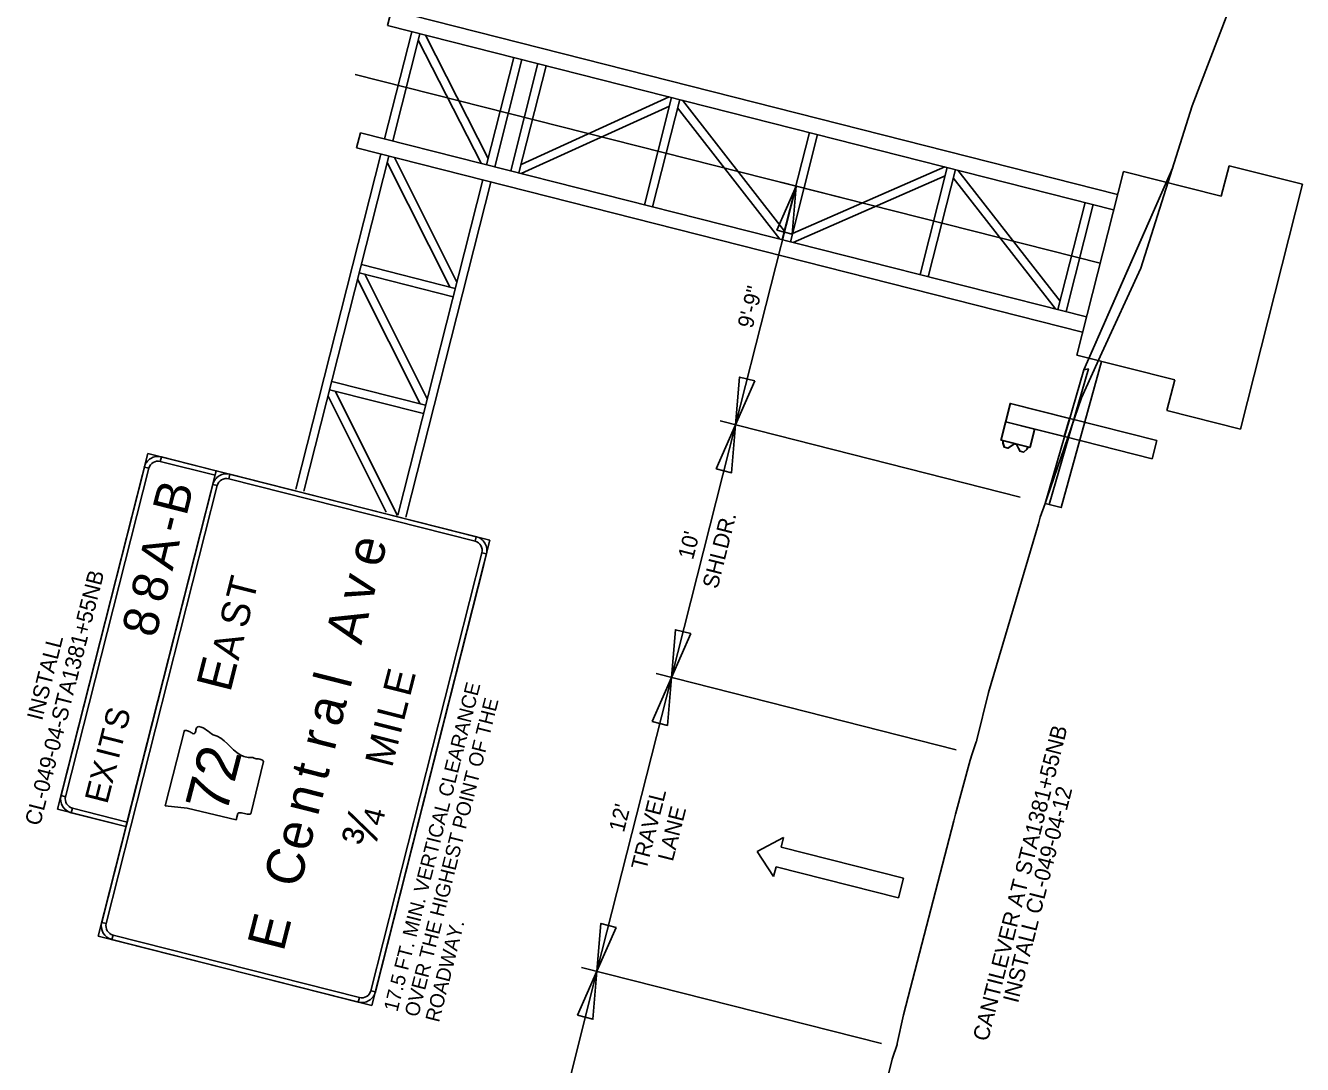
# Model space of a CAD drawing. Extents: x 670006 to 670131, y 737844 to 738002.
# Drawn here: x 670068.6 to 670119.1, y 737920.9 to 737962 of the extents above; entities that cross this region are included whole.
import ezdxf

# ---------------------------------------------------------------- set-up
doc = ezdxf.new("R2010")
doc.units = 0
for name, color, linetype in [('R_Alt Surface', 7, 'Continuous'), ('R_Exist Surface', 7, 'Continuous'), ('R_Fin Surface', 7, 'Continuous'), ('R_Guardrail', 7, 'Continuous'), ('R_MOT', 7, 'Continuous'), ('R_Proposed Const Limits', 7, 'Continuous'), ('R_SIGN', 7, 'Continuous'), ('R_SIGN_ANNOT', 7, 'Continuous')]:
    doc.layers.add(name, color=color, linetype=linetype)

msp = doc.modelspace()

# ---------------------------------------------------------------- linework, layer by layer
at = {"layer": 'R_Alt Surface'}
msp.add_lwpolyline([(670109.08, 737943.044), (670109.565, 737942.921), (670111.156, 737948.707)], dxfattribs=at)
at = {"layer": 'R_Exist Surface'}
msp.add_lwpolyline([(670101.41, 737915.266), (670102.87, 737921.083), (670102.88, 737921.115), (670103.063, 737921.667), (670103.071, 737921.706), (670103.315, 737922.841), (670105.306, 737930.515), (670105.374, 737930.778), (670105.958, 737932.918), (670105.978, 737932.992), (670105.979, 737932.995), (670106.006, 737933.094), (670106.197, 737933.644), (670106.205, 737933.663), (670106.219, 737933.721), (670106.688, 737935.597), (670108.659, 737942.277), (670108.734, 737942.533), (670108.919, 737943.085), (670109.001, 737943.32), (670110.364, 737947.269), (670111.175, 737949.039), (670112.711, 737952.403), (670113.874, 737956.065), (670114.748, 737958.822), (670116.463, 737963.305)], dxfattribs=at)
at = {"layer": 'R_Fin Surface'}
for points in [[(670108.919, 737943.085), (670110.458, 737948.368), (670112.079, 737952.061), (670113.975, 737956.382)], [(670108.919, 737943.085), (670110.458, 737948.368)]]:
    msp.add_lwpolyline(points, dxfattribs=at)
msp.add_lwpolyline([(670108.919, 737943.085), (670109.08, 737943.044), (670110.64, 737948.408), (670110.458, 737948.368)], close=True, dxfattribs=at)
at = {"layer": 'R_Guardrail'}
for points in [[(670107.355, 737946.318), (670107.539, 737947.045), (670109.885, 737946.45), (670109.672, 737945.731)], [(670107.355, 737946.318), (670107.539, 737947.045), (670109.885, 737946.45), (670109.672, 737945.731)], [(670107.368, 737946.315), (670107.552, 737947.042), (670109.898, 737946.447), (670109.688, 737945.727)], [(670107.171, 737945.591), (670107.355, 737946.318), (670108.5, 737946.028), (670108.315, 737945.301)], [(670107.171, 737945.591), (670107.355, 737946.318), (670108.5, 737946.028), (670108.315, 737945.301)], [(670107.184, 737945.588), (670107.368, 737946.315), (670108.513, 737946.025), (670108.329, 737945.298)], [(670107.247, 737945.572), (670107.244, 737945.471), (670107.306, 737945.308), (670107.445, 737945.273), (670107.696, 737945.445), (670107.784, 737945.422), (670107.923, 737945.151), (670108.062, 737945.116), (670108.194, 737945.23), (670108.239, 737945.32)], [(670107.247, 737945.572), (670107.244, 737945.471), (670107.306, 737945.308), (670107.445, 737945.273), (670107.696, 737945.445), (670107.784, 737945.422), (670107.923, 737945.151), (670108.062, 737945.116), (670108.194, 737945.23), (670108.239, 737945.32)], [(670107.26, 737945.569), (670107.257, 737945.468), (670107.319, 737945.305), (670107.458, 737945.269), (670107.709, 737945.441), (670107.797, 737945.419), (670107.936, 737945.148), (670108.075, 737945.113), (670108.207, 737945.227), (670108.252, 737945.317)]]:
    msp.add_lwpolyline(points, close=True, dxfattribs=at)
for points in [[(670113.158, 737944.846), (670109.688, 737945.727), (670109.898, 737946.447), (670113.343, 737945.573)], [(670113.158, 737944.846), (670113.343, 737945.573)]]:
    msp.add_lwpolyline(points, dxfattribs=at)
at = {"layer": 'R_MOT'}
for p, q in [((670098.568, 737929.861), (670097.521, 737929.302)), ((670098.469, 737929.474), (670098.568, 737929.861)), ((670097.521, 737929.302), (670098.174, 737928.31)), ((670103.312, 737928.245), (670098.469, 737929.474)), ((670098.174, 737928.31), (670098.273, 737928.698)), ((670098.273, 737928.698), (670103.115, 737927.47)), ((670103.115, 737927.47), (670103.312, 737928.245))]:
    msp.add_line(p, q, dxfattribs=at)
at = {"layer": 'R_Proposed Const Limits'}
msp.add_lwpolyline([(670110.458, 737948.368), (670113.975, 737956.382)], dxfattribs=at)
at = {"layer": 'R_SIGN'}
for p, q in [((670082.888, 737962.002), (670083.041, 737962.608)), ((670111.79, 737955.317), (670083.041, 737962.608)), ((670082.769, 737957.519), (670083.845, 737961.759)), ((670111.637, 737954.711), (670082.888, 737962.002)), ((670083.092, 737957.437), (670084.168, 737961.677)), ((670086.871, 737956.744), (670084.387, 737961.622)), ((670086.589, 737956.55), (670084.104, 737961.427)), ((670086.808, 737956.494), (670087.884, 737960.735)), ((670087.131, 737956.412), (670088.207, 737960.653)), ((670111.099, 737952.59), (670081.607, 737960.07)), ((670087.764, 737956.252), (670088.839, 737960.493)), ((670088.087, 737956.17), (670089.162, 737960.411)), ((670088.172, 737956.506), (670094.037, 737959.174)), ((670093.059, 737954.909), (670094.134, 737959.15)), ((670093.382, 737954.827), (670094.457, 737959.068)), ((670088.184, 737956.145), (670094.049, 737958.813)), ((670098.414, 737953.551), (670094.374, 737958.738)), ((670098.6, 737953.855), (670094.559, 737959.042)), ((670081.659, 737957.156), (670081.812, 737957.761)), ((670110.561, 737950.47), (670081.812, 737957.761)), ((670098.516, 737953.525), (670099.591, 737957.766)), ((670098.839, 737953.443), (670099.915, 737957.684)), ((670110.408, 737949.864), (670081.659, 737957.156)), ((670079.251, 737943.645), (670082.616, 737956.913)), ((670079.574, 737943.563), (670082.939, 737956.831)), ((670082.875, 737956.579), (670085.348, 737951.651)), ((670083.157, 737956.776), (670085.629, 737951.848)), ((670104.947, 737956.407), (670098.923, 737953.773)), ((670104.965, 737956.051), (670098.941, 737953.417)), ((670103.973, 737952.141), (670105.049, 737956.382)), ((670104.296, 737952.059), (670105.372, 737956.3)), ((670109.514, 737951.087), (670105.473, 737956.274)), ((670110.177, 737948.955), (670112.021, 737956.225)), ((670115.898, 737955.242), (670112.021, 737956.225)), ((670115.898, 737955.242), (670116.205, 737956.454)), ((670119.113, 737955.716), (670116.205, 737956.454)), ((670083.289, 737942.621), (670086.654, 737955.889)), ((670083.612, 737942.539), (670086.977, 737955.807)), ((670109.329, 737950.783), (670105.288, 737955.97)), ((670119.113, 737955.716), (670116.655, 737946.023)), ((670109.43, 737950.757), (670110.506, 737954.998)), ((670109.753, 737950.675), (670110.829, 737954.916)), ((670085.566, 737951.596), (670081.85, 737952.538)), ((670085.482, 737951.266), (670081.766, 737952.209)), ((670081.984, 737952.153), (670084.457, 737947.225)), ((670081.702, 737951.957), (670084.175, 737947.029)), ((670114.054, 737947.972), (670110.177, 737948.955)), ((670113.747, 737946.76), (670114.054, 737947.972)), ((670084.31, 737946.644), (670080.594, 737947.586)), ((670084.393, 737946.974), (670080.678, 737947.916)), ((670080.812, 737947.531), (670083.285, 737942.603)), ((670080.53, 737947.335), (670082.838, 737942.736)), ((670116.655, 737946.023), (670113.747, 737946.76)), ((670073.394, 737945.063), (670069.821, 737930.974)), ((670076.103, 737944.376), (670073.394, 737945.063)), ((670073.89, 737944.745), (670073.936, 737944.925)), ((670073.257, 737944.521), (670073.437, 737944.475)), ((670076.103, 737944.376), (670071.431, 737925.952)), ((670072.53, 737930.287), (670076.103, 737944.376)), ((670086.94, 737941.627), (670076.103, 737944.376)), ((670076.599, 737944.058), (670076.645, 737944.238)), ((670075.966, 737943.834), (670076.146, 737943.788)), ((670082.268, 737923.204), (670086.94, 737941.627)), ((670086.399, 737941.764), (670086.353, 737941.584)), ((670086.816, 737941.135), (670082.393, 737923.696)), ((670086.622, 737941.131), (670086.803, 737941.085)), ((670074.075, 737931.111), (670074.853, 737934.1)), ((670074.853, 737934.1), (670074.892, 737934.099)), ((670074.853, 737934.1), (670074.853, 737934.1)), ((670074.892, 737934.099), (670074.93, 737934.093)), ((670074.93, 737934.093), (670074.966, 737934.083)), ((670074.966, 737934.083), (670075.001, 737934.069)), ((670075.001, 737934.069), (670075.035, 737934.052)), ((670075.035, 737934.052), (670075.069, 737934.034)), ((670075.069, 737934.034), (670075.102, 737934.014)), ((670075.102, 737934.014), (670075.135, 737933.994)), ((670075.135, 737933.994), (670075.167, 737933.975)), ((670075.167, 737933.975), (670075.2, 737933.957)), ((670075.2, 737933.957), (670075.237, 737933.976)), ((670075.237, 737933.976), (670075.263, 737934.004)), ((670075.263, 737934.004), (670075.28, 737934.04)), ((670075.28, 737934.04), (670075.291, 737934.081)), ((670075.291, 737934.081), (670075.3, 737934.122)), ((670075.3, 737934.122), (670075.309, 737934.161)), ((670075.309, 737934.161), (670075.323, 737934.197)), ((670075.323, 737934.197), (670075.343, 737934.225)), ((670075.343, 737934.225), (670075.372, 737934.244)), ((670075.372, 737934.244), (670075.414, 737934.25)), ((670075.414, 737934.25), (670075.502, 737934.229)), ((670075.502, 737934.229), (670075.58, 737934.198)), ((670075.58, 737934.198), (670075.652, 737934.158)), ((670075.652, 737934.158), (670075.718, 737934.112)), ((670075.718, 737934.112), (670075.783, 737934.063)), ((670075.783, 737934.063), (670075.848, 737934.015)), ((670075.848, 737934.015), (670075.914, 737933.967)), ((670075.914, 737933.967), (670075.983, 737933.925)), ((670075.983, 737933.925), (670076.058, 737933.889)), ((670076.058, 737933.889), (670076.141, 737933.864)), ((670076.141, 737933.864), (670076.287, 737933.783)), ((670076.287, 737933.783), (670076.42, 737933.68)), ((670076.42, 737933.68), (670076.544, 737933.566)), ((670076.544, 737933.566), (670076.666, 737933.446)), ((670076.666, 737933.446), (670076.787, 737933.328)), ((670076.787, 737933.328), (670076.913, 737933.219)), ((670076.913, 737933.219), (670077.049, 737933.128)), ((670077.049, 737933.128), (670077.2, 737933.061)), ((670077.2, 737933.061), (670077.368, 737933.025)), ((670077.368, 737933.025), (670077.558, 737933.029)), ((670077.98, 737932.867), (670077.476, 737930.798)), ((670077.558, 737933.029), (670077.599, 737933.003)), ((670077.599, 737933.003), (670077.643, 737932.986)), ((670077.643, 737932.986), (670077.689, 737932.976)), ((670077.689, 737932.976), (670077.736, 737932.97)), ((670077.736, 737932.97), (670077.783, 737932.965)), ((670077.783, 737932.965), (670077.829, 737932.959)), ((670077.829, 737932.959), (670077.874, 737932.949)), ((670077.874, 737932.949), (670077.913, 737932.932)), ((670077.913, 737932.932), (670077.95, 737932.906)), ((670077.95, 737932.906), (670077.98, 737932.867)), ((670070.139, 737931.47), (670069.958, 737931.516)), ((670069.821, 737930.974), (670072.53, 737930.287)), ((670070.363, 737930.837), (670070.408, 737931.018)), ((670074.957, 737931.016), (670074.075, 737931.111)), ((670076.893, 737930.562), (670074.957, 737931.016)), ((670076.954, 737930.802), (670076.893, 737930.562)), ((670077.002, 737930.827), (670076.954, 737930.802)), ((670077.053, 737930.837), (670077.002, 737930.827)), ((670077.107, 737930.835), (670077.053, 737930.837)), ((670077.163, 737930.824), (670077.107, 737930.835)), ((670077.219, 737930.809), (670077.163, 737930.824)), ((670077.275, 737930.794), (670077.219, 737930.809)), ((670077.329, 737930.781), (670077.275, 737930.794)), ((670077.381, 737930.775), (670077.329, 737930.781)), ((670077.431, 737930.779), (670077.381, 737930.775)), ((670077.476, 737930.798), (670077.431, 737930.779)), ((670072.53, 737930.287), (670072.53, 737930.287)), ((670071.749, 737926.448), (670071.568, 737926.494)), ((670071.431, 737925.952), (670082.268, 737923.204)), ((670071.973, 737925.815), (670072.018, 737925.995)), ((670082.405, 737923.746), (670082.225, 737923.791)), ((670081.772, 737923.522), (670081.726, 737923.341)), ((670082.268, 737923.204), (670082.268, 737923.204))]:
    msp.add_line(p, q, dxfattribs=at)
for points in [[(670076.057, 737944.195), (670073.89, 737944.745), (670073.936, 737944.925), (670076.103, 737944.376), (670076.057, 737944.195)], [(670073.437, 737944.475), (670070.139, 737931.47), (670069.958, 737931.516), (670073.257, 737944.521), (670073.437, 737944.475)], [(670086.353, 737941.584), (670076.599, 737944.058), (670076.645, 737944.238), (670086.399, 737941.764), (670086.353, 737941.584)], [(670076.146, 737943.788), (670071.749, 737926.448), (670071.568, 737926.494), (670075.966, 737943.834), (670076.146, 737943.788)], [(670082.225, 737923.791), (670086.622, 737941.131), (670086.803, 737941.085), (670082.405, 737923.746), (670082.225, 737923.791)], [(670070.408, 737931.018), (670072.576, 737930.468), (670072.53, 737930.287), (670070.363, 737930.837), (670070.408, 737931.018)], [(670072.018, 737925.995), (670081.772, 737923.522), (670081.726, 737923.341), (670071.973, 737925.815), (670072.018, 737925.995)]]:
    msp.add_lwpolyline(points, close=True, dxfattribs=at)
msp.add_lwpolyline([(670086.693, 737940.65), (670082.514, 737924.172)], dxfattribs=at)
for centre, radius, start, end in [((670073.798, 737944.383), 0.559, 75.7686, 165.7688), ((670073.798, 737944.383), 0.373, 75.7686, 165.7688), ((670076.508, 737943.696), 0.559, 75.7686, 165.7688), ((670076.508, 737943.696), 0.373, 75.7686, 165.7688), ((670086.261, 737941.223), 0.373, 345.7686, 75.7688), ((670086.261, 737941.223), 0.559, 345.7686, 75.7688), ((670070.5, 737931.379), 0.559, 165.7688, 255.7684), ((670070.5, 737931.379), 0.373, 165.7688, 255.7684), ((670072.11, 737926.357), 0.559, 165.7688, 255.7684), ((670072.11, 737926.357), 0.373, 165.7688, 255.7684), ((670081.863, 737923.883), 0.559, 255.7684, 345.7686), ((670081.863, 737923.883), 0.373, 255.7684, 345.7686)]:
    msp.add_arc(centre, radius, start, end, dxfattribs=at)
at = {"layer": 'R_SIGN_ANNOT'}
for p, q in [((670096.665, 737946.192), (670099.062, 737955.643)), ((670101.204, 737955.1), (670098.456, 737955.797)), ((670094.128, 737936.19), (670096.665, 737946.192)), ((670107.937, 737943.334), (670096.059, 737946.346)), ((670105.4, 737933.331), (670093.522, 737936.343)), ((670091.178, 737924.558), (670094.128, 737936.19)), ((670102.45, 737921.699), (670090.572, 737924.712)), ((670088.228, 737912.926), (670091.178, 737924.558))]:
    msp.add_line(p, q, dxfattribs=at)
for points in [[(670098.298, 737953.903), (670099.062, 737955.643), (670098.904, 737953.749)], [(670097.429, 737947.933), (670096.665, 737946.192), (670096.823, 737948.087)], [(670095.901, 737944.452), (670096.665, 737946.192), (670096.507, 737944.298)], [(670094.892, 737937.93), (670094.128, 737936.19), (670094.286, 737938.084)], [(670093.364, 737934.449), (670094.128, 737936.19), (670093.97, 737934.296)], [(670091.942, 737926.299), (670091.178, 737924.558), (670091.336, 737926.452)], [(670090.414, 737922.817), (670091.178, 737924.558), (670091.02, 737922.664)]]:
    msp.add_lwpolyline(points, close=True, dxfattribs=at)

# ---------------------------------------------------------------- texts
at = {"layer": 'R_SIGN'}
for s, height, rotation, p in [('B', 1.398, 75.7686, (670074.919, 737942.547)), ('-', 1.398, 75.7686, (670074.74, 737941.843)), ('A', 1.398, 75.7686, (670074.369, 737940.38)), ('e', 1.491, 75.7686, (670082.618, 737940.501)), ('v', 1.491, 75.7686, (670082.262, 737939.099)), ('8', 1.398, 75.7686, (670074.042, 737939.093)), ('T', 1.118, 75.7686, (670077.564, 737939.135)), ('8', 1.398, 75.7686, (670073.695, 737937.724)), ('S', 1.118, 75.7686, (670077.3, 737938.094)), ('A', 1.491, 75.7686, (670081.845, 737937.452)), ('A', 1.118, 75.7686, (670076.982, 737936.837)), ('E', 1.398, 75.7686, (670076.656, 737935.564)), ('l', 1.491, 75.7686, (670081.405, 737935.718)), ('E', 1.118, 75.7686, (670083.773, 737935.393)), ('a', 1.491, 75.7686, (670081.016, 737934.187)), ('S', 0.932, 75.7686, (670072.527, 737934.065)), ('L', 1.118, 75.7686, (670083.526, 737934.418)), ('I', 1.118, 75.7686, (670083.394, 737933.897)), ('T', 0.932, 75.7686, (670072.323, 737933.262)), ('r', 1.491, 75.7686, (670080.778, 737933.247)), ('M', 1.118, 75.7686, (670083.062, 737932.586)), ('I', 0.932, 75.7686, (670072.236, 737932.918)), ('2', 1.687, 75.407, (670076.814, 737931.983)), ('X', 0.932, 75.7686, (670071.989, 737931.943)), ('t', 1.491, 75.7686, (670080.47, 737932.034)), ('7', 1.687, 75.407, (670076.495, 737930.747)), ('E', 0.932, 75.7686, (670071.787, 737931.148)), ('n', 1.491, 75.7686, (670080.122, 737930.661)), ('¾', 1.398, 75.7686, (670082.387, 737929.357)), ('e', 1.491, 75.7686, (670079.767, 737929.259)), ('C', 1.491, 75.7686, (670079.4, 737927.814)), ('E', 1.491, 75.7686, (670078.763, 737925.3))]:
    msp.add_text(s, height=height, rotation=rotation, dxfattribs=at).set_placement(p)
at = {"layer": 'R_SIGN_ANNOT'}
for s, height, p in [('9\'-9"', 0.625, (670097.336, 737949.98)), ('SHLDR.', 0.625, (670095.951, 737939.671)), ("10'", 0.625, (670094.981, 737940.824)), ('CL-049-04-STA1381+55NB', 0.63, (670069.125, 737930.288)), ('INSTALL', 0.63, (670069.208, 737934.458)), ('17.5 FT. MIN. VERTICAL CLEARANCE ', 0.567, (670083.275, 737922.929)), ('OVER THE HIGHEST POINT OF THE ', 0.567, (670084.099, 737922.72)), ('CANTILEVER AT STA1381+55NB', 0.625, (670106.656, 737921.755)), ('INSTALL CL-049-04-12', 0.625, (670107.848, 737923.272)), ('TRAVEL', 0.625, (670093.127, 737928.533)), ("12'", 0.625, (670092.244, 737930.031)), ('LANE', 0.625, (670094.182, 737928.88)), ('ROADWAY.', 0.567, (670084.924, 737922.511))]:
    msp.add_text(s, height=height, rotation=75.7686, dxfattribs=at).set_placement(p)

doc.saveas('drawing.dxf')
